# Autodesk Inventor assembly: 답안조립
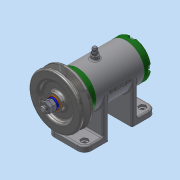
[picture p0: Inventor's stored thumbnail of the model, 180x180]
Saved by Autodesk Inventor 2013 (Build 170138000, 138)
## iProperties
Created: 2017-02
Part Number: 답안조립
Document SubType Name: Assembly
Designer: dgall
Author: dgall
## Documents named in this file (16)
- C:\Users\dgall\Desktop\470207V1031\답안조립.iam
- C:\Users\dgall\Desktop\470207V1031\본체.ipt
- C:\Users\dgall\Desktop\470207V1031\V벨트풀리.ipt
- C:\Users\dgall\Desktop\470207V1031\너트 M 8.ipt
- C:\Users\dgall\Desktop\470207V1031\니플 M 6 x 0.75.ipt
- C:\Users\dgall\Desktop\470207V1031\뒤커버.ipt
- C:\Users\dgall\Desktop\470207V1031\베어링 15 x 32 x 9.ipt
- C:\Users\dgall\Desktop\470207V1031\볼트 M 6 x 8.ipt
- C:\Users\dgall\Desktop\470207V1031\볼트 M4 x 12.ipt
- C:\Users\dgall\Desktop\470207V1031\스프링와셔 8.ipt
- C:\Users\dgall\Desktop\470207V1031\앞커버.ipt
- C:\Users\dgall\Desktop\470207V1031\오일 실 15 25 7.ipt
- C:\Users\dgall\Desktop\470207V1031\와셔 6x11.5.ipt
- C:\Users\dgall\Desktop\470207V1031\와셔 8x17.ipt
- C:\Users\dgall\Desktop\470207V1031\축.ipt
- C:\Users\dgall\Desktop\470207V1031\키 3 x 3 x 12.ipt
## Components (11 placed, 3 different names)
1. V벨트풀리:1
2. KS B 2023 6002 - 15 x 32 x 9:1
3. KS B 2023 6002 - 15 x 32 x 9:2
4. ISO 4762 M4 x 12:1
5. ISO 4762 M4 x 12:3
6. ISO 4762 M4 x 12:4
7. ISO 4762 M4 x 12:5
8. ISO 4762 M4 x 12:2
9. ISO 4762 M4 x 12:6
10. ISO 4762 M4 x 12:7
11. ISO 4762 M4 x 12:8
